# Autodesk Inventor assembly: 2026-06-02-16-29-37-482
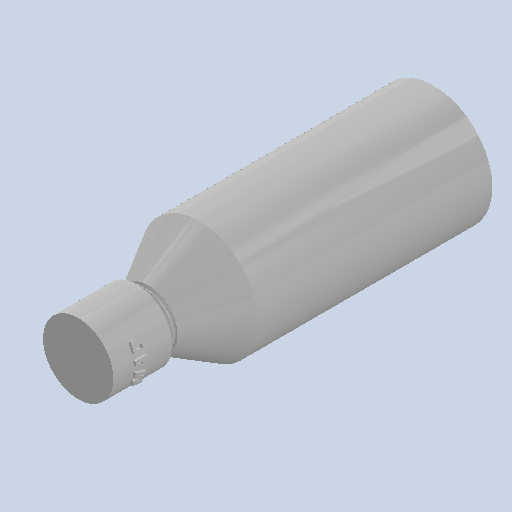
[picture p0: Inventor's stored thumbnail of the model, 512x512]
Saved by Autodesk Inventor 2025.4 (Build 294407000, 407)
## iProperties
Created: 2026-06
Part Number: 2026-06-02-16-29-37-482
Document SubType Name: Assembly
Designer: AdminForWorker
Title: lil-lunje bottle v2
Author: AdminForWorker
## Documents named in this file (3)
- c:\worker\convert-fusion-r03-cosv3\tmp\job-1\46\temp\files\6ced6a51-cc59-466f-a1fa-505b3553f15e\4c8cd9c7-8020-4cdd-9b43-435c093d2172.iam
- c:\worker\convert-fusion-r03-cosv3\tmp\job-1\46\temp\files\6ced6a51-cc59-466f-a1fa-505b3553f15e\BOTTLE v1.ipt
- c:\worker\convert-fusion-r03-cosv3\tmp\job-1\46\temp\files\6ced6a51-cc59-466f-a1fa-505b3553f15e\LID v2.ipt
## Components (2 placed, 2 different names)
1. BOTTLE v1:1
2. LID v2:1
